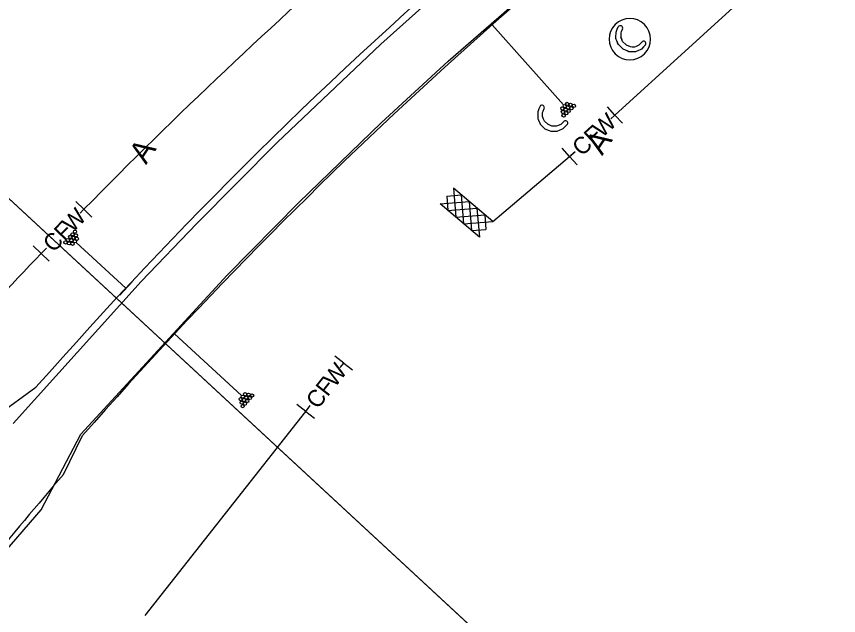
# Model space of a CAD drawing. Extents: x 2357856 to 2382083, y 331121 to 347536.
# Drawn here: x 2380554 to 2380922.9, y 332459.7 to 332728.7 of the extents above; entities that cross this region are included whole.
import ezdxf

# ---------------------------------------------------------------- set-up
doc = ezdxf.new("R2010")
doc.units = 0
for name, color, linetype in [('_CIVIL_CONSTRUCTION', 7, 'Continuous'), ('Coir Fiber Wattle Both CELL', 7, 'Continuous'), ('Default', 7, 'Continuous'), ('Matting and PSRM Summary Sheet CELL', 7, 'Continuous'), ('Old_Level_12', 7, 'Continuous'), ('P_NCDOT_Horizontal_Alignment_Station_Label', 7, 'Continuous'), ('P_NCDOT_Horizontal_Alignment_Tick_Small', 7, 'Continuous'), ('Sheet Data Field CELL', 7, 'Continuous'), ('Sheet_Named_Boundary', 7, 'Continuous')]:
    doc.layers.add(name, color=color, linetype=linetype)

# ---------------------------------------------------------------- blocks, each defined once
blk = doc.blocks.new('SCA1')
at = {"layer": '_CIVIL_CONSTRUCTION'}
for p, q in [((-0.00583, 0.0038), (-0.00964, 0)), ((-0.00963, 0.00383), (0.00963, 0.00383)), ((-0.00193, 0.00383), (-0.00963, -0.00387)), ((-0.00193, -0.00387), (-0.00963, 0.00383)), ((0.00193, 0.00383), (-0.0058, -0.00387)), ((0.00193, -0.00387), (-0.0058, 0.00383)), ((0.00577, 0.00384), (-0.00193, -0.00387)), ((0.00577, -0.00387), (-0.00193, 0.00383)), ((0.00963, 0.00383), (0.00193, -0.00387)), ((0.00963, -0.00387), (0.00193, 0.00383)), ((0.00964, 0), (0.00577, 0.00384)), ((-0.0058, -0.00387), (-0.00964, 0)), ((0.00964, 0), (0.00577, -0.00387)), ((-0.00963, -0.00387), (0.00963, -0.00387))]:
    blk.add_line(p, q, dxfattribs=at)

msp = doc.modelspace()

# ---------------------------------------------------------------- linework, layer by layer
at = {"layer": 'Coir Fiber Wattle Both CELL'}
for p, q in [((2380545.07, 332549.52), (2380562.74, 332562.2)), ((2380575.08, 332523.07), (2380583.68, 332540.58))]:
    msp.add_line(p, q, dxfattribs=at)
for radius, start, end in [(2080, 122.68319, 138.66863), (2050, 124.90194, 138.73574), (2045, 139.26365, 142.29397)]:
    msp.add_arc((2382124.62, 331188.54), radius, start, end, dxfattribs=at)
at = {"layer": 'Default'}
for points in [[(2380245.38, 332929.65), (2381505.45, 333788.59), (2382082.78, 332941.65), (2381016.75, 332214.98)], [(2379358.12, 331688.32), (2380202.89, 332957.93), (2380245.38, 332929.65), (2380969.09, 332259.14), (2380211.47, 331120.52)]]:
    msp.add_lwpolyline(points, close=True, dxfattribs=at)
at = {"layer": 'Matting and PSRM Summary Sheet CELL'}
for p, q in [((2380822.55, 332684.46), (2380819.18, 332688.15)), ((2380820.7, 332682.77), (2380822.55, 332684.46)), ((2380822.55, 332684.46), (2380825.92, 332680.76)), ((2380802.17, 332665.87), (2380798.8, 332669.56)), ((2380802.17, 332665.87), (2380804.02, 332667.55)), ((2380802.17, 332665.87), (2380805.54, 332662.17)), ((2380802.76, 332666.38), (2380804.61, 332668.07)), ((2380584.29, 332642.13), (2380580.7, 332645.61)), ((2380582.55, 332640.33), (2380584.29, 332642.13)), ((2380584.29, 332642.13), (2380587.88, 332638.65)), ((2380565.1, 332622.32), (2380561.51, 332625.8)), ((2380565.1, 332622.32), (2380566.84, 332624.11)), ((2380565.1, 332622.32), (2380568.69, 332618.84)), ((2380565.66, 332622.87), (2380567.4, 332624.66)), ((2380700.82, 332573.09), (2380696.89, 332576.18)), ((2380699.28, 332571.13), (2380700.82, 332573.09)), ((2380700.82, 332573.09), (2380704.75, 332570)), ((2380683.79, 332551.4), (2380679.85, 332554.49)), ((2380683.79, 332551.4), (2380685.33, 332553.37)), ((2380684.29, 332552.01), (2380685.83, 332553.97)), ((2380683.79, 332551.4), (2380687.72, 332548.31))]:
    msp.add_line(p, q, dxfattribs=at)
at = {"layer": 'Old_Level_12'}
for p, q in [((2380764.19, 332722.25), (2380770.28, 332727.67)), ((2380799.46, 332688.99), (2380767.38, 332724.9)), ((2380580.71, 332627.28), (2380603.01, 332606.68)), ((2380605.93, 332609.62), (2380600.38, 332603.64)), ((2380622.04, 332583.28), (2380627.59, 332589.27)), ((2380655, 332558.5), (2380624.96, 332586.22))]:
    msp.add_line(p, q, dxfattribs=at)
for centre, major_axis in [((2380798.91, 332687.41), (-0.499, 0.559)), ((2380799.96, 332688.43), (-0.499, 0.559)), ((2380801.09, 332689.45), (-0.499, 0.559)), ((2380801.47, 332687.84), (-0.499, 0.559)), ((2380802.65, 332689.08), (-0.499, 0.559)), ((2380803.02, 332687.56), (-0.499, 0.559)), ((2380804.16, 332688.57), (-0.499, 0.559)), ((2380799.19, 332685.81), (-0.499, 0.559)), ((2380799.47, 332684.22), (-0.499, 0.559)), ((2380800.37, 332686.87), (-0.499, 0.559)), ((2380800.66, 332685.27), (-0.499, 0.559)), ((2380801.79, 332686.29), (-0.499, 0.559)), ((2380580.24, 332632.03), (0.55, -0.509)), ((2380577.03, 332628.37), (0.55, -0.509)), ((2380578.13, 332629.75), (0.55, -0.509)), ((2380578.6, 332628.23), (0.55, -0.509)), ((2380579.17, 332630.87), (0.55, -0.509)), ((2380579.6, 332629.31), (0.55, -0.509)), ((2380580.67, 332630.47), (0.55, -0.509)), ((2380581.11, 332628.91), (0.55, -0.509)), ((2380575.99, 332627.25), (0.55, -0.509)), ((2380577.54, 332626.89), (0.55, -0.509)), ((2380579.13, 332626.67), (0.55, -0.509)), ((2380580.16, 332627.79), (0.55, -0.509)), ((2380656.58, 332559.11), (-0.55, 0.509)), ((2380658.17, 332558.89), (-0.55, 0.509)), ((2380659.72, 332558.53), (-0.55, 0.509)), ((2380654.6, 332556.87), (-0.55, 0.509)), ((2380655.04, 332555.31), (-0.55, 0.509)), ((2380655.55, 332557.99), (-0.55, 0.509)), ((2380656.11, 332556.47), (-0.55, 0.509)), ((2380656.54, 332554.91), (-0.55, 0.509)), ((2380657.1, 332557.54), (-0.55, 0.509)), ((2380657.58, 332556.03), (-0.55, 0.509)), ((2380658.68, 332557.41), (-0.55, 0.509)), ((2380655.47, 332553.74), (-0.55, 0.509))]:
    msp.add_ellipse(centre, major_axis=major_axis, ratio=0.927398, dxfattribs=at)
at = {"layer": 'P_NCDOT_Horizontal_Alignment_Station_Label'}
for p, q in [((2380825.4, 332721.93), (2380825.15, 332721.35)), ((2380825.15, 332721.35), (2380825.15, 332720.46)), ((2380825.89, 332723.07), (2380825.4, 332721.93)), ((2380825.15, 332720.46), (2380825.14, 332719.3)), ((2380825.22, 332719.13), (2380825.14, 332719.3)), ((2380825.22, 332719.13), (2380825.59, 332718.32)), ((2380825.98, 332717.46), (2380825.59, 332718.32)), ((2380825.98, 332717.46), (2380827.5, 332716)), ((2380827.51, 332716), (2380827.5, 332716)), ((2380827.51, 332716), (2380829.37, 332715.17)), ((2380829.37, 332715.17), (2380830.33, 332715.14)), ((2380830.33, 332715.14), (2380831.49, 332715.1)), ((2380831.49, 332715.1), (2380832.24, 332715.43)), ((2380832.24, 332715.43), (2380833.33, 332715.91)), ((2380833.51, 332716.09), (2380833.33, 332715.91)), ((2380833.51, 332716.09), (2380834.55, 332717.16)), ((2380790.11, 332683.44), (2380790.03, 332683.61)), ((2380790.87, 332681.76), (2380790.48, 332682.63)), ((2380792.4, 332680.3), (2380792.39, 332680.31)), ((2380798.4, 332680.4), (2380798.22, 332680.21))]:
    msp.add_line(p, q, dxfattribs=at)
for points in [[(2380836.28, 332716.01), (2380835.42, 332715.1), (2380834.42, 332714.05), (2380833.81, 332713.78), (2380833.07, 332713.45), (2380831.76, 332712.88), (2380831.73, 332712.88), (2380831.37, 332712.88), (2380831.31, 332712.88), (2380830.55, 332712.88), (2380830.01, 332712.89), (2380828.84, 332712.9), (2380828.07, 332713.22), (2380826.2, 332714.02), (2380826.19, 332714.02), (2380824.68, 332715.5), (2380824.09, 332716.08), (2380823.74, 332716.91), (2380823.67, 332717.09), (2380823.37, 332717.79), (2380823.14, 332718.33), (2380823.09, 332718.46), (2380822.98, 332718.73), (2380822.97, 332718.74), (2380822.99, 332719.94), (2380823.01, 332721.02), (2380823.02, 332721.67), (2380823.56, 332722.96), (2380824.04, 332724.11)], [(2380788.93, 332688.41), (2380788.45, 332687.27), (2380787.91, 332685.97), (2380787.9, 332685.32), (2380787.88, 332684.25), (2380787.86, 332683.04), (2380787.87, 332683.03), (2380787.98, 332682.76), (2380788.03, 332682.64), (2380788.26, 332682.1), (2380788.56, 332681.39), (2380788.63, 332681.21), (2380788.98, 332680.38), (2380789.57, 332679.8), (2380791.08, 332678.33), (2380791.08, 332678.32), (2380792.96, 332677.53), (2380793.73, 332677.2), (2380794.9, 332677.19), (2380795.44, 332677.19), (2380796.2, 332677.18), (2380796.26, 332677.18), (2380796.61, 332677.18), (2380796.65, 332677.18), (2380797.96, 332677.76), (2380798.7, 332678.08), (2380799.31, 332678.35), (2380800.31, 332679.41), (2380801.17, 332680.31)], [(2380799.44, 332681.46), (2380798.4, 332680.4), (2380798.22, 332680.21), (2380797.13, 332679.74), (2380796.38, 332679.41), (2380795.22, 332679.44), (2380794.26, 332679.47), (2380792.4, 332680.3), (2380792.39, 332680.31), (2380790.87, 332681.76), (2380790.48, 332682.63), (2380790.11, 332683.44), (2380790.03, 332683.61), (2380790.03, 332684.77), (2380790.04, 332685.65), (2380790.29, 332686.23), (2380790.78, 332687.37), (2380790.78, 332687.37)]]:
    msp.add_lwpolyline(points, dxfattribs=at)
for centre, radius, start, end in [((2380829.21, 332718.52), 9.29, 56.361, 146.361), ((2380829.21, 332718.52), 9.29, 326.361, 56.361), ((2380829.21, 332718.52), 9.29, 146.361, 236.361), ((2380824.93, 332723.51), 1.07, 335.2483, 146.361), ((2380835.42, 332716.58), 1.04, 326.361, 146.361), ((2380829.21, 332718.52), 9.29, 236.361, 326.361), ((2380789.81, 332687.82), 1.07, 335.2483, 146.361), ((2380800.31, 332680.89), 1.04, 326.361, 146.361)]:
    msp.add_arc(centre, radius, start, end, dxfattribs=at)
at = {"layer": 'Sheet Data Field CELL'}
for points in [[(2381104.38, 332997.7), (2381069.47, 332977.56), (2381040.56, 332960.19), (2381010.45, 332941.41), (2380956.28, 332905.78), (2380930.1, 332887.68), (2380906.38, 332870.75), (2380877.19, 332849.22), (2380826.88, 332810.21), (2380788.53, 332778.76), (2380751.41, 332746.82), (2380717.5, 332716.27), (2380671.02, 332672.12), (2380634.87, 332635.81), (2380609.99, 332609.75), (2380552.58, 332545.97)], [(2380531.76, 332468.65), (2380565, 332507.19), (2380582.89, 332541.2), (2380648.52, 332612.53), (2380680.76, 332645.21), (2380717.67, 332680.89), (2380747.68, 332708.62), (2380808.05, 332761.2), (2380852.12, 332797.07), (2380899.23, 332833.24), (2380937.38, 332860.99), (2380975.7, 332887.54), (2381012.85, 332912.08), (2381058.61, 332940.75), (2381095.37, 332962.59), (2381137.68, 332988.81)]]:
    msp.add_lwpolyline(points, dxfattribs=at)
at = {"layer": 'Sheet_Named_Boundary'}
for p, q in [((2380822.55, 332684.46), (2380949.84, 332800.56)), ((2380611.79, 332459.73), (2380683.79, 332551.4))]:
    msp.add_line(p, q, dxfattribs=at)
msp.add_lwpolyline([(2380767.67, 332636.65), (2380802.17, 332665.87)], dxfattribs=at)
for start, end in [(131.24605, 135.58734), (136.26014, 139.21866)]:
    msp.add_arc((2382262.22, 330998.25), 2349, start, end, dxfattribs=at)

# ---------------------------------------------------------------- block references
at = {"layer": '_CIVIL_CONSTRUCTION', "xscale": 1199.9999999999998, "yscale": 1199.9999999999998, "rotation": 139.63084050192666}
msp.add_blockref('SCA1', (2380755.86, 332640.6), dxfattribs=at)

# ---------------------------------------------------------------- texts
at = {"layer": 'Matting and PSRM Summary Sheet CELL'}
for s, rotation, p in [('W', 42.3685, (2380816.76, 332673.93)), ('F', 42.3685, (2380812.88, 332670.41)), ('C', 42.3685, (2380807.6, 332665.6)), ('W', 45.9161, (2380579.17, 332631.27)), ('F', 45.9161, (2380575.51, 332627.51)), ('C', 45.9161, (2380570.54, 332622.38)), ('W', 51.8541, (2380696.85, 332561.75)), ('F', 51.8541, (2380693.6, 332557.65)), ('C', 51.8541, (2380689.19, 332552.03))]:
    msp.add_text(s, height=7.54, rotation=rotation, dxfattribs=at).set_placement(p)
at = {"layer": 'P_NCDOT_Horizontal_Alignment_Tick_Small'}
for p in [(2380816.81, 332665.94), (2380612.13, 332661.93)]:
    msp.add_text('A', height=10, rotation=56.361, dxfattribs=at).set_placement(p)

doc.saveas('drawing.dxf')
